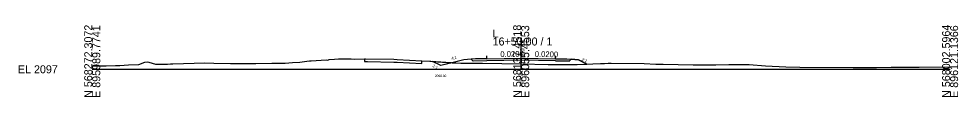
# Model space of a CAD drawing. Extents: x -26 to 1603, y -10 to 13527.
# Drawn here: x -25.7 to 302.8, y 3990.3 to 4015.5 of the extents above; entities that cross this region are included whole.
import ezdxf

# ---------------------------------------------------------------- set-up
doc = ezdxf.new("R2010")
doc.units = 0
for name, color, linetype in [('Default', 7, 'Continuous'), ('Exist XS Center Line Elevation Label', 7, 'Continuous'), ('Exist XS Ground Line', 7, 'Continuous'), ('Old_Level_61', 7, 'Continuous'), ('Old_Level_63', 7, 'Continuous'), ('Prop XS Ditch Slope Text', 7, 'Continuous'), ('Prop XS Ditch Standard Text', 7, 'Continuous'), ('Prop XS Earthwork Shape', 7, 'Continuous'), ('Prop XS EOT Tick Mark', 7, 'Continuous'), ('Prop XS Finish Grade', 7, 'Continuous'), ('Prop XS Finish Grade Earthwork', 7, 'Continuous'), ('Prop XS Finish Grade Paved Shoulder', 7, 'Continuous'), ('Prop XS Finish Grade Pavement', 7, 'Continuous'), ('Prop XS Side Slope Text', 7, 'Continuous'), ('Prop XS Subgrade Earthwork', 7, 'Continuous'), ('Prop XSC Text', 7, 'Continuous')]:
    doc.layers.add(name, color=color, linetype=linetype)

msp = doc.modelspace()

# ---------------------------------------------------------------- linework, layer by layer
at = {"layer": 'Exist XS Ground Line'}
for p, q in [((12.66, 4001.51), (16.31, 4001.66)), ((16.31, 4001.66), (18.43, 4002.54)), ((18.43, 4002.54), (19.19, 4002.61)), ((19.19, 4002.61), (19.8, 4002.46)), ((19.8, 4002.46), (22.12, 4001.81)), ((22.12, 4001.81), (26.29, 4001.85)), ((26.29, 4001.85), (27.39, 4001.88)), ((27.39, 4001.88), (28.13, 4001.91)), ((28.13, 4001.91), (39.38, 4002.3)), ((39.38, 4002.3), (42.54, 4002.18)), ((42.54, 4002.18), (48.35, 4002)), ((48.35, 4002), (57.18, 4002.06)), ((57.18, 4002.06), (62.85, 4002.09)), ((62.85, 4002.09), (67.41, 4002.1)), ((67.41, 4002.1), (70.05, 4002.35)), ((70.05, 4002.35), (72.65, 4002.44)), ((72.65, 4002.44), (75.05, 4002.83)), ((75.05, 4002.83), (75.96, 4002.97)), ((75.96, 4002.97), (76.6, 4003.01)), ((76.6, 4003.01), (81.8, 4003.27)), ((81.8, 4003.27), (82.35, 4003.25)), ((82.35, 4003.25), (82.9, 4003.43)), ((82.9, 4003.43), (84.76, 4003.6)), ((84.76, 4003.6), (86.09, 4003.62)), ((86.09, 4003.62), (87.49, 4003.61)), ((87.49, 4003.61), (90.59, 4003.64)), ((90.59, 4003.64), (91.62, 4003.6)), ((91.62, 4003.6), (95.24, 4003.71)), ((95.24, 4003.71), (95.59, 4003.7)), ((95.59, 4003.7), (105.43, 4003.52)), ((105.43, 4003.52), (106.61, 4003.45)), ((106.61, 4003.45), (115.28, 4003)), ((115.28, 4003), (118.05, 4002.84)), ((118.05, 4002.84), (118.41, 4002.82)), ((118.41, 4002.82), (128.87, 4002.09)), ((128.87, 4002.09), (130.64, 4002.14)), ((130.64, 4002.14), (136.49, 4002.16)), ((136.49, 4002.16), (150, 4001.9)), ((150, 4001.9), (159.42, 4001.71)), ((159.42, 4001.71), (169.6, 4001.68)), ((169.6, 4001.68), (177.69, 4002)), ((177.69, 4002), (179.11, 4002.07)), ((179.11, 4002.07), (180.42, 4002.09)), ((180.42, 4002.09), (181.45, 4002.09)), ((181.45, 4002.09), (192.96, 4001.99)), ((192.96, 4001.99), (197.11, 4001.81)), ((197.11, 4001.81), (199.61, 4001.78)), ((199.61, 4001.78), (210.13, 4001.53)), ((210.13, 4001.53), (218.04, 4001.58)), ((218.04, 4001.58), (222.63, 4001.69)), ((222.63, 4001.69), (229.7, 4001.73)), ((229.7, 4001.73), (235.41, 4001.16)), ((0, 4001.16), (4.86, 4001.24)), ((4.86, 4001.24), (8.08, 4001.29)), ((8.08, 4001.29), (9.66, 4001.33)), ((9.66, 4001.33), (12.66, 4001.51)), ((235.41, 4001.16), (242.53, 4000.89)), ((242.53, 4000.89), (247.48, 4000.75)), ((247.48, 4000.75), (266.08, 4000.64)), ((266.08, 4000.64), (272.34, 4000.57)), ((272.34, 4000.57), (274.25, 4000.64)), ((274.25, 4000.64), (279.41, 4000.69)), ((279.41, 4000.69), (289.2, 4000.79)), ((289.2, 4000.79), (300, 4000.81))]:
    msp.add_line(p, q, dxfattribs=at)
at = {"layer": 'Old_Level_61'}
for p, q in [((95.24, 4003.71), (95.24, 4002.71)), ((95.24, 4002.71), (95.59, 4002.7)), ((95.24, 4002.71), (95.24, 4002.71)), ((95.59, 4002.7), (96.24, 4002.69)), ((96.24, 4002.69), (105.43, 4002.52)), ((105.43, 4002.52), (106.61, 4002.45)), ((106.61, 4002.45), (115.28, 4002)), ((115.28, 4002), (115.28, 4003))]:
    msp.add_line(p, q, dxfattribs=at)
at = {"layer": 'Old_Level_63'}
for p, q in [((150, 4000), (150, 4011.13)), ((0, 4000), (150, 4000)), ((150, 4000), (300, 4000))]:
    msp.add_line(p, q, dxfattribs=at)
at = {"layer": 'Prop XS Earthwork Shape'}
for points in [[(121.93, 4001.3), (118.97, 4002.78), (125.92, 4002.29)], [(136.49, 4002.16), (150, 4001.9), (159.42, 4001.71), (169.6, 4001.68), (172.97, 4001.82), (170, 4003.3), (167.5, 4003.5), (166.81, 4002.81), (162, 4002.91), (150, 4003.15), (138, 4002.91), (133.17, 4002.81), (132.48, 4003.5), (129.97, 4003.3), (125.92, 4002.29), (128.87, 4002.09), (130.64, 4002.14)]]:
    msp.add_lwpolyline(points, close=True, dxfattribs=at)
at = {"layer": 'Prop XS EOT Tick Mark'}
for p, q in [((138, 4003.7), (138, 4004.7)), ((162, 4003.7), (162, 4004.7))]:
    msp.add_line(p, q, dxfattribs=at)
at = {"layer": 'Prop XS Finish Grade'}
for p, q in [((133.98, 4003.62), (132.48, 4003.5)), ((166, 4003.62), (167.5, 4003.5))]:
    msp.add_line(p, q, dxfattribs=at)
at = {"layer": 'Prop XS Finish Grade Earthwork'}
for p, q in [((121.93, 4001.3), (118.97, 4002.78)), ((129.97, 4003.3), (121.93, 4001.3)), ((132.48, 4003.5), (129.97, 4003.3)), ((167.5, 4003.5), (170, 4003.3)), ((170, 4003.3), (172.97, 4001.82))]:
    msp.add_line(p, q, dxfattribs=at)
at = {"layer": 'Prop XS Finish Grade Paved Shoulder'}
for p, q in [((138, 4003.7), (133.98, 4003.62)), ((162, 4003.7), (166, 4003.62))]:
    msp.add_line(p, q, dxfattribs=at)
at = {"layer": 'Prop XS Finish Grade Pavement'}
for p, q in [((138, 4003.7), (150, 4003.94)), ((150, 4003.94), (162, 4003.7))]:
    msp.add_line(p, q, dxfattribs=at)
at = {"layer": 'Prop XS Subgrade Earthwork'}
for p, q in [((133.17, 4002.81), (132.48, 4003.5)), ((138, 4002.91), (133.17, 4002.81)), ((150, 4003.15), (138, 4002.91)), ((162, 4002.91), (150, 4003.15)), ((162, 4002.91), (166.81, 4002.81)), ((166.81, 4002.81), (167.5, 4003.5))]:
    msp.add_line(p, q, dxfattribs=at)

# ---------------------------------------------------------------- texts
at = {"layer": 'Default'}
for rotation, p in [(1.1458, (142.73, 4004.29)), (358.8542, (154.73, 4004.35))]:
    msp.add_text('0.0200', height=2, rotation=rotation, dxfattribs=at).set_placement(p)
at = {"layer": 'Exist XS Center Line Elevation Label'}
msp.add_text('2098.90', height=1, rotation=90, dxfattribs=at).set_placement((150.5, 3994.05))
at = {"layer": 'Old_Level_63'}
for s, p in [('N 568272.3072', (0, 3990)), ('E 895989.7741', (2.8, 3990)), ('N 568137.4518', (150, 3990)), ('E 896055.4553', (152.8, 3990)), ('N 568002.5964', (300, 3990)), ('E 896121.1366', (302.8, 3990))]:
    msp.add_text(s, height=2.8, rotation=90, dxfattribs=at).set_placement(p)
for s, p in [('L', (140, 4011.13)), ('16+50.00 / 1', (140, 4008.33)), ('EL 2097', (-26, 3998.6))]:
    msp.add_text(s, height=2.8, dxfattribs=at).set_placement(p)
at = {"layer": 'Prop XS Ditch Slope Text'}
msp.add_text('4:1', height=1, rotation=13.9814, dxfattribs=at).set_placement((125.71, 4003.27))
at = {"layer": 'Prop XS Ditch Standard Text'}
msp.add_text('2098.30', height=0.8, dxfattribs=at).set_placement((119.83, 3997.3))
at = {"layer": 'Prop XS Side Slope Text'}
for rotation, p in [(333.5282, (118.9, 4000.88)), (333.4349, (171.08, 4003.14))]:
    msp.add_text('2:1', height=1, rotation=rotation, dxfattribs=at).set_placement(p)
at = {"layer": 'Prop XSC Text'}
msp.add_text(' 2100.94', height=1.2, rotation=90, dxfattribs=at).set_placement((151.2, 4003.94))

doc.saveas('drawing.dxf')
